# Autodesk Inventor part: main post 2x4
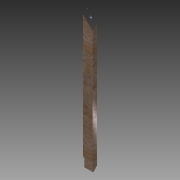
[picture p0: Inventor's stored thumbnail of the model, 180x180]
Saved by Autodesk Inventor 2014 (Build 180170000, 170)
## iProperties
Created: 2013-07
Part Number: main post 2x4
Material: Generic
Document SubType Name: Modeling
Designer: Patrick Rice
Density: 1 g/cm^3
Appearance: Default
Author: Patrick Rice
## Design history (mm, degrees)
sketch "Sketch1"
  geometry: L1 (44.45, -19.05)-(-44.45, -19.05); L2 (-44.45, -19.05)-(-44.45, 19.05); L3 (-44.45, 19.05)-(44.45, 19.05); L4 (44.45, 19.05)-(44.45, -19.05); L5 (44.45, -19.05)-(-44.45, 19.05); L6 (-44.45, -19.05)-(44.45, 19.05); 1 further point
  constraints: 12 end point, 2 midpoint, 2 parallel, 1 horizontal, 1 perpendicular
  dimensions: "d0" = 88.9 distance of L2.end L3.end; "d1" = 38.1 distance of L1.end L2.end
extrude "Extrusion1" new body sketch "Sketch1" distance "d2" = 1219.2; taper "d3" = 0 deg
hole "Hole1" diameter "d6" = 6.35; stored, may be unused: countersink angle "d10" = 82 deg, drill point angle "d12" = 118 deg; dims "d4" = 44.45, "d5" = 44.45, "d7" = 19.05, "d8" = 19.05, "d9" = 12.7, "d11" = 25.4
hole "Hole3" diameter "d24" = 6.35; stored, may be unused: countersink angle "d28" = 82 deg, drill point angle "d30" = 118 deg; dims "d22" = 44.45, "d23" = 273.05, "d25" = 19.05, "d26" = 19.05, "d27" = 12.7, "d29" = 25.4
hole "Hole4" diameter "d33" = 6.35; stored, may be unused: countersink angle "d37" = 82 deg, drill point angle "d39" = 118 deg; dims "d31" = 635, "d32" = 44.45, "d34" = 19.05, "d35" = 19.05, "d36" = 12.7, "d38" = 25.4
hole "Hole5" diameter "d42" = 6.35; stored, may be unused: countersink angle "d46" = 82 deg, drill point angle "d48" = 118 deg; dims "d40" = 44.45, "d43" = 19.05, "d44" = 19.05, "d45" = 12.7, "d47" = 25.4, "d50" = 698.5
body "Solid1"
